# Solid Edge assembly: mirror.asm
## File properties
Author: Owner
Template: Metric Assembly.asm
Last saved by: Lee
Revision: 13
Application: Solid Edge
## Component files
mirror_alone.par
CF_mirror_backing.par
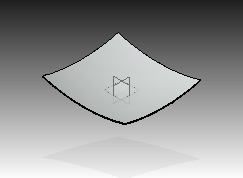
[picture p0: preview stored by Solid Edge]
